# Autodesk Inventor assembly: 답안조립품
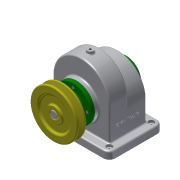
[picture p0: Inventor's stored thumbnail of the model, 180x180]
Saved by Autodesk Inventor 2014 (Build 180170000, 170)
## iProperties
Created: 2017-11
Part Number: 답안조립품
Document SubType Name: Assembly
Designer: user
Author: user
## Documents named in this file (12)
- C:\Users\user\Desktop\471108V1007\답안조립품.iam
- C:\Users\user\Desktop\471108V1007\본체.ipt
- C:\Users\user\Desktop\471108V1007\축.ipt
- C:\Users\user\Desktop\471108V1007\V-벨트풀리.ipt
- C:\Users\user\Desktop\471108V1007\멈춤나사 - M4 x 10.ipt
- 멈춤나사 - M4 x 10.ipt
- C:\Users\user\Desktop\471108V1007\앞커버.ipt
- C:\Users\user\Desktop\471108V1007\볼트 M3 x 8.ipt
- C:\Users\user\Desktop\471108V1007\베어링 6002.ipt
- C:\Users\user\Desktop\471108V1007\오일 실 15 30 7.ipt
- C:\Users\user\Desktop\471108V1007\키 - 6 x 6 x 22.ipt
- C:\Users\user\Desktop\471108V1007\뒤커버.ipt
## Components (1 placed, 1 different names)
1. V-벨트풀리:1
